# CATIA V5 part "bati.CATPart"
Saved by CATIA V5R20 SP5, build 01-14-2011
Part number: bati
Publications: "Corps principal", "Droite.1", "Droite.2", "Plan.1"
Bounding box of the stored display mesh (mm): x 0 to 70, y 0 to 670, z 161.91 to 221.91
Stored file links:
  M:\EU_thinkMotion\IAO_2010\iao\IAO_MMS_Groupe2\IAO_MMS_Groupe2\rwatrin\rwatrin\bati.CATPart
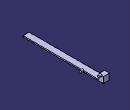
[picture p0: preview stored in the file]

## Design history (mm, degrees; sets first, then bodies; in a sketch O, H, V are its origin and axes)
Parameters
  xA = 539.859 mm
  yb = 40 mm
  xb = 650 mm
  `Longueur bati` = 670 mm
Set1
  Point1: type OnCurve, Support edge [face of Pad1 from Sketch1.L1 | face of Pad1 from Sketch1.L7], Ratio 0.5
  Line1: type PtDir, RefPoint Point1, Direction xy-plane, Start 87, End 0
  Point2: type OnCurve, Support edge [face of Pad1 from Sketch1.L6 | face of Pad1 from Sketch1.L5], Ratio 0.5
  Plane1: type Tangent, Support face of Pad1 from Sketch1.L7, RefPoint {point type OnPlane, Support face of Pad1 from Sketch1.L7, H 28.578, V 18.693, Direction (1, 0, 0)}
Body1 (main body)
  Sketch1 on yz-plane, origin (0, 0, 0), H (0, 1, 0), V (0, 0, 1)
    line L1 (0, 171.91) -> (0, 161.91)
    line L2 (0, 161.91) -> (670, 161.91)
    line L3 (670, 161.91) -> (670, 30)
    line L4 (670, 30) -> (670, 211.91)
    line L5 (670, 211.91) -> (630, 211.91)
    line L6 (630, 211.91) -> (630, 171.91)
    line L7 (630, 171.91) -> (0, 171.91)
    axis line L8 (590, 211.91) -> (-40, 211.91)
    point P8 (590, 211.91)
    length L6 = 40 {= yb}
    length L2 = 670 {= `Longueur bati`}
    length L5 = 40
    length L1 = 10
    vertical: L1 V, L3 V, L4 V, L6 V
    horizontal: L2 H, L5 H, L7 H, L8 H
    coincidence: L1 V, P8 L5, L8 L5
    parallelism: L8 L5
    fix: L8, L5
  Pad1: profile Sketch1, direction (1, 0, 0), length 50
  Sketch2 on end face of Pad1, origin (50, 0, 0), H (0, 1, 0), V (0, 0, 1)
    circle A1 centre (500, 171.91) radius 10
    point P1 (500, 171.91)
    circle A2 centre (650, 211.91) radius 10
    point P2 (650, 211.91)
    reference projected line E1 (0, 30) -> (0, 0) from edge [face of Pad1 from Sketch1.L1 | end face of Pad1]
    reference projected line E2 (160, 211.91) -> (130, 211.91) from edge [face of Pad1 from Sketch1.L5 | end face of Pad1]
    reference projected line E3 (130, 171.91) -> (-70, 171.91) from edge [face of Pad1 from Sketch1.L7 | end face of Pad1]
    reference intersected line E4 (0, 161.91) -> (0, 171.91) from face of Pad1 from Sketch1.L1
    distance E1 P2 = 650 {= xb}
    radius A2 = 10
    radius A1 = 10
    distance P1 E4 = 500
    coincidence: P2 E2, P1 E3
  Pad2: profile Sketch2, direction (1, 0, 0), length 20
